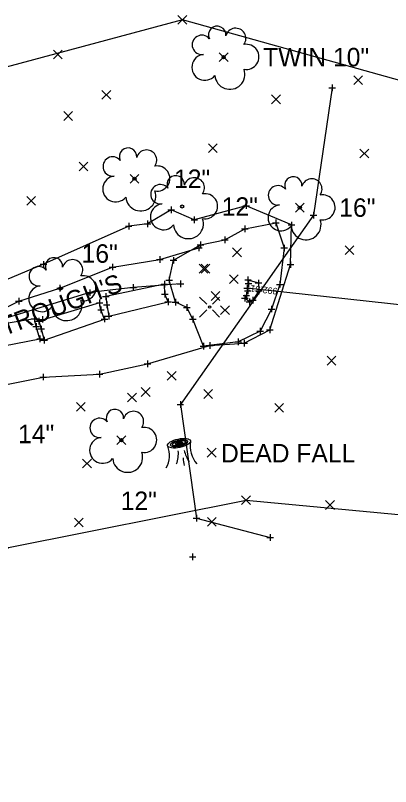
# Model space of a CAD drawing. Extents: x 160138 to 160780, y 488720 to 491073.
# Drawn here: x 160617.3 to 160674.2, y 489637.9 to 489754.9 of the extents above; entities that cross this region are included whole.
import ezdxf

# ---------------------------------------------------------------- set-up
doc = ezdxf.new("R2010")
doc.units = 0
for name, color, linetype in [('_CIVIL_CONSTRUCTION', 7, 'Continuous'), ('DR_X_Storm_Sewer', 7, 'Continuous'), ('GE_X_Alignment_500_Distances', 7, 'Continuous'), ('RD_X_Concrete_Pad', 7, 'Continuous'), ('RD_X_Text', 7, 'Continuous'), ('RS_Raster1', 7, 'Continuous'), ('RW_X_CL_100_Curve_Data', 7, 'Continuous'), ('RW_X_CL_100_Stations', 7, 'Continuous'), ('SC_Scratch1', 7, 'Continuous'), ('SV_P_Control_Cells_Set', 7, 'Continuous'), ('SV_P_Mon_Cells_Set', 7, 'Continuous'), ('SV_X_Mon_Cells_Found', 7, 'Continuous'), ('SV_X_Random_Point', 7, 'Continuous'), ('SV_X_Terrain_Boundary', 7, 'Continuous'), ('VG_X_Text', 7, 'Continuous'), ('VG_X_Tree_Line_Lt', 7, 'Continuous')]:
    doc.layers.add(name, color=color, linetype=linetype)

msp = doc.modelspace()

# ---------------------------------------------------------------- linework, layer by layer
at = {"layer": '_CIVIL_CONSTRUCTION'}
for p, q in [((160641.93, 489753.59), (160643.26, 489754.92)), ((160641.93, 489754.92), (160643.26, 489753.59)), ((160623.01, 489748.32), (160624.34, 489749.66)), ((160623.01, 489749.66), (160624.34, 489748.32)), ((160648.2, 489747.93), (160649.53, 489749.27)), ((160648.2, 489749.27), (160649.53, 489747.93)), ((160668.62, 489744.44), (160669.96, 489745.77)), ((160668.62, 489745.77), (160669.96, 489744.44)), ((160630.38, 489742.19), (160631.72, 489743.53)), ((160630.38, 489743.53), (160631.72, 489742.19)), ((160656.14, 489741.52), (160657.48, 489742.85)), ((160656.14, 489742.85), (160657.48, 489741.52)), ((160624.6, 489738.99), (160625.93, 489740.33)), ((160624.6, 489740.33), (160625.93, 489738.99)), ((160646.57, 489734.1), (160647.9, 489735.43)), ((160646.57, 489735.43), (160647.9, 489734.1)), ((160669.56, 489733.31), (160670.9, 489734.65)), ((160669.56, 489734.65), (160670.9, 489733.31)), ((160626.94, 489731.34), (160628.27, 489732.67)), ((160626.94, 489732.67), (160628.27, 489731.34)), ((160634.67, 489729.47), (160636, 489730.8)), ((160634.67, 489730.8), (160636, 489729.47)), ((160618.99, 489726.11), (160620.32, 489727.44)), ((160618.99, 489727.44), (160620.32, 489726.11)), ((160659.75, 489725.09), (160661.09, 489726.43)), ((160659.75, 489726.43), (160661.09, 489725.09)), ((160650.23, 489718.29), (160651.56, 489719.63)), ((160650.23, 489719.63), (160651.56, 489718.29)), ((160667.3, 489718.64), (160668.64, 489719.98)), ((160667.3, 489719.98), (160668.64, 489718.64)), ((160645.15, 489715.81), (160646.48, 489717.15)), ((160645.15, 489717.15), (160646.48, 489715.81)), ((160645.46, 489715.82), (160646.79, 489717.16)), ((160645.46, 489717.16), (160646.79, 489715.82)), ((160649.75, 489714.25), (160651.08, 489715.58)), ((160649.75, 489715.58), (160651.08, 489714.25)), ((160646.97, 489711.68), (160648.3, 489713.01)), ((160646.97, 489713.01), (160648.3, 489711.68)), ((160648.39, 489709.53), (160649.73, 489710.86)), ((160648.39, 489710.86), (160649.73, 489709.53)), ((160664.58, 489701.85), (160665.91, 489703.19)), ((160664.58, 489703.19), (160665.91, 489701.85)), ((160640.3, 489699.57), (160641.64, 489700.91)), ((160640.3, 489700.91), (160641.64, 489699.57)), ((160636.36, 489697.11), (160637.69, 489698.45)), ((160636.36, 489698.45), (160637.69, 489697.11)), ((160634.29, 489696.29), (160635.62, 489697.62)), ((160634.29, 489697.62), (160635.62, 489696.29)), ((160645.86, 489696.79), (160647.19, 489698.13)), ((160645.86, 489698.13), (160647.19, 489696.79)), ((160626.51, 489694.86), (160627.84, 489696.19)), ((160626.51, 489696.19), (160627.84, 489694.86)), ((160656.61, 489694.71), (160657.94, 489696.05)), ((160656.61, 489696.05), (160657.94, 489694.71)), ((160632.67, 489689.8), (160634.01, 489691.13)), ((160632.67, 489691.13), (160634.01, 489689.8)), ((160646.37, 489687.91), (160647.71, 489689.25)), ((160646.37, 489689.25), (160647.71, 489687.91)), ((160627.44, 489686.25), (160628.78, 489687.59)), ((160627.44, 489687.59), (160628.78, 489686.25)), ((160651.6, 489680.69), (160652.94, 489682.02)), ((160651.6, 489682.02), (160652.94, 489680.69)), ((160664.34, 489679.96), (160665.67, 489681.29)), ((160664.34, 489681.29), (160665.67, 489679.96)), ((160626.2, 489677.29), (160627.53, 489678.63)), ((160626.2, 489678.63), (160627.53, 489677.29)), ((160646.39, 489677.41), (160647.72, 489678.75)), ((160646.39, 489678.75), (160647.72, 489677.41))]:
    msp.add_line(p, q, dxfattribs=at)
at = {"layer": 'DR_X_Storm_Sewer'}
msp.add_line((160736.14, 489704.3), (160652.45, 489713.55), dxfattribs=at)
at = {"layer": 'GE_X_Alignment_500_Distances'}
msp.add_lwpolyline([(160606.81, 489697.08), (160621.48, 489700.05), (160630.02, 489700.49), (160637.32, 489702.04), (160646.76, 489704.84), (160651.99, 489705.18), (160655.89, 489707.19), (160659.01, 489717.1), (160659.18, 489723.12), (160652.27, 489726.05), (160644.41, 489723.92), (160640.91, 489725.41), (160637.3, 489723.29), (160634.45, 489722.96), (160621.53, 489717.15), (160606.18, 489710.76)], dxfattribs=at)
at = {"layer": 'RD_X_Concrete_Pad'}
for points in [[(160640.46, 489711.46), (160639.94, 489712.63), (160639.86, 489714.15), (160630.99, 489712.27), (160631.11, 489711.01), (160631.41, 489709.3)], [(160630.76, 489708.85), (160630.24, 489710.26), (160630.04, 489711.29), (160620.79, 489708.54), (160621.17, 489707.34), (160621.61, 489705.66)], [(160620.98, 489705.83), (160620.39, 489707.73), (160620.16, 489708.89), (160611.14, 489707.39), (160611.67, 489705.22), (160611.8, 489704.05)]]:
    msp.add_lwpolyline(points, close=True, dxfattribs=at)
at = {"layer": 'RS_Raster1'}
for p, q in [((160651.95, 489713.55), (160652.95, 489713.55)), ((160652.45, 489714.05), (160652.45, 489713.05)), ((160652.45, 489713.55), (160652.45, 489713.55)), ((160620.84, 489708.8), (160621.84, 489708.8)), ((160621.34, 489709.3), (160621.34, 489708.3)), ((160621.34, 489708.8), (160621.34, 489708.8))]:
    msp.add_line(p, q, dxfattribs=at)
at = {"layer": 'RW_X_CL_100_Curve_Data'}
msp.add_lwpolyline([(160656.8, 489723.43), (160658.06, 489719.63), (160657.41, 489714.11), (160656.13, 489710.37), (160654.42, 489707.03), (160651.09, 489705.4), (160645.8, 489704.75), (160644.2, 489708.84), (160643.27, 489710.59), (160641.57, 489711.39), (160640.61, 489714.75), (160641.25, 489717.76), (160645.36, 489720.12), (160649.06, 489720.86), (160652.09, 489722.54)], close=True, dxfattribs=at)
at = {"layer": 'RW_X_CL_100_Stations'}
msp.add_lwpolyline([(160652.52, 489713.11), (160652.62, 489714.25), (160652.56, 489714.79), (160654.15, 489714.32), (160654.21, 489713.12), (160653.28, 489711.73), (160652.77, 489711.46), (160652.08, 489712.01), (160652.31, 489712.41)], close=True, dxfattribs=at)
at = {"layer": 'SC_Scratch1'}
msp.add_line((160642.46, 489688.49), (160642.46, 489688.49), dxfattribs=at)
for centre in [(160648.86, 489748.6), (160635.33, 489730.14), (160642.57, 489725.92), (160660.42, 489725.76), (160624.1, 489713.48), (160633.34, 489690.47)]:
    msp.add_circle(centre, 0.24, dxfattribs=at)
for centre, radius, start, end in [((160647.88, 489751.97), 1.32, 354.0047, 205.9741), ((160650.69, 489751.43), 1.55, 323.83, 165.0376), ((160645.55, 489750.46), 1.47, 39.0625, 279.5412), ((160652.32, 489748.63), 1.91, 259.1453, 101.4596), ((160646.01, 489747.05), 1.97, 96.1722, 320.5737), ((160649.81, 489745.99), 2.28, 184.9476, 19.4572), ((160634.35, 489733.5), 1.32, 354.0047, 205.9741), ((160632.02, 489732), 1.47, 39.0625, 279.5412), ((160637.16, 489732.96), 1.55, 323.83, 165.0376), ((160638.79, 489730.17), 1.91, 259.1453, 101.4596), ((160632.48, 489728.59), 1.97, 96.1722, 320.5737), ((160641.59, 489729.29), 1.32, 354.0047, 205.9741), ((160644.4, 489728.75), 1.55, 323.83, 165.0376), ((160659.44, 489729.13), 1.32, 354.0047, 205.9741), ((160662.25, 489728.59), 1.55, 323.83, 165.0376), ((160639.26, 489727.79), 1.47, 39.0625, 279.5412), ((160657.11, 489727.62), 1.47, 39.0625, 279.5412), ((160636.28, 489727.53), 2.28, 184.9476, 19.4572), ((160646.03, 489725.96), 1.91, 259.1453, 101.4596), ((160663.88, 489725.79), 1.91, 259.1453, 101.4596), ((160639.72, 489724.37), 1.97, 96.1722, 320.5737), ((160657.57, 489724.21), 1.97, 96.1722, 320.5737), ((160643.52, 489723.32), 2.28, 184.9476, 19.4572), ((160661.37, 489723.15), 2.28, 184.9476, 19.4572), ((160623.11, 489716.85), 1.32, 354.0047, 205.9741), ((160625.92, 489716.31), 1.55, 323.83, 165.0376), ((160620.79, 489715.35), 1.47, 39.0625, 279.5412), ((160627.56, 489713.52), 1.91, 259.1453, 101.4596), ((160621.24, 489711.93), 1.97, 96.1722, 320.5737), ((160625.04, 489710.88), 2.28, 184.9476, 19.4572), ((160632.36, 489693.83), 1.32, 354.0047, 205.9741), ((160635.17, 489693.3), 1.55, 323.83, 165.0376), ((160630.03, 489692.33), 1.47, 39.0625, 279.5412), ((160636.8, 489690.5), 1.91, 259.1453, 101.4596), ((160630.49, 489688.92), 1.97, 96.1722, 320.5737), ((160648.07, 489689.63), 4.29, 171.4106, 219.9194), ((160636.63, 489688.15), 4, 331.5338, 20.9269), ((160648.97, 489690.55), 6.32, 194.9653, 212.1216), ((160634.29, 489687.86), 2.28, 184.9476, 19.4572), ((160636.94, 489688.52), 5.05, 340.7938, 3.5481), ((160646.37, 489687.69), 3.64, 178.7926, 197.1224)]:
    msp.add_arc(centre, radius, start, end, dxfattribs=at)
for major_axis in [(1.74, 0.37), (1.3, 0.28), (0.976, 0.211), (0.549, 0.119), (0.309, 0.067)]:
    msp.add_ellipse((160642.09, 489690), major_axis=major_axis, ratio=0.36865, dxfattribs=at)
at = {"layer": 'SV_P_Control_Cells_Set'}
msp.add_lwpolyline([(160570.79, 489697.1), (160575.87, 489695.84), (160582.13, 489698.19), (160589.99, 489701.08), (160597.61, 489703.89), (160611.48, 489708.49), (160617.77, 489711.56), (160624.02, 489713.54), (160631.98, 489716.74), (160639.19, 489717.9), (160645.11, 489719.67)], dxfattribs=at)
at = {"layer": 'SV_P_Mon_Cells_Set'}
msp.add_lwpolyline([(160642.3, 489714.2), (160635.13, 489713.64), (160628.55, 489712.85), (160611, 489707.49), (160597, 489702.59), (160583.66, 489697.45), (160573.76, 489689.28), (160563.37, 489687.48)], dxfattribs=at)
at = {"layer": 'SV_X_Mon_Cells_Found'}
for p, q in [((160645.22, 489712.17), (160646.31, 489711.08)), ((160647.15, 489711.08), (160648.24, 489712.17)), ((160645.22, 489709.15), (160646.31, 489710.24)), ((160647.15, 489710.24), (160648.24, 489709.15))]:
    msp.add_line(p, q, dxfattribs=at)
msp.add_circle((160646.73, 489710.67), 0.17, dxfattribs=at)
at = {"layer": 'SV_X_Random_Point'}
for p, q in [((160664.84, 489743.92), (160665.84, 489743.92)), ((160665.34, 489744.42), (160665.34, 489743.42)), ((160665.34, 489743.92), (160665.34, 489743.92)), ((160652.27, 489726.55), (160652.27, 489725.55)), ((160640.41, 489725.41), (160641.41, 489725.41)), ((160640.91, 489725.91), (160640.91, 489724.91)), ((160640.91, 489725.41), (160640.91, 489725.41)), ((160651.77, 489726.05), (160652.77, 489726.05)), ((160652.27, 489726.05), (160652.27, 489726.05)), ((160644.41, 489724.42), (160644.41, 489723.42)), ((160662.01, 489724.6), (160663.01, 489724.6)), ((160662.51, 489725.1), (160662.51, 489724.1)), ((160662.51, 489724.6), (160662.51, 489724.6)), ((160633.95, 489722.96), (160634.95, 489722.96)), ((160634.45, 489723.46), (160634.45, 489722.46)), ((160634.45, 489722.96), (160634.45, 489722.96)), ((160636.8, 489723.29), (160637.8, 489723.29)), ((160637.3, 489723.79), (160637.3, 489722.79)), ((160637.3, 489723.29), (160637.3, 489723.29)), ((160643.91, 489723.92), (160644.91, 489723.92)), ((160644.41, 489723.92), (160644.41, 489723.92)), ((160652.09, 489723.04), (160652.09, 489722.04)), ((160656.3, 489723.43), (160657.3, 489723.43)), ((160656.8, 489723.93), (160656.8, 489722.93)), ((160656.8, 489723.43), (160656.8, 489723.43)), ((160658.68, 489723.12), (160659.68, 489723.12)), ((160659.18, 489723.62), (160659.18, 489722.62)), ((160659.18, 489723.12), (160659.18, 489723.12)), ((160651.59, 489722.54), (160652.59, 489722.54)), ((160652.09, 489722.54), (160652.09, 489722.54)), ((160645.36, 489720.62), (160645.36, 489719.62)), ((160648.56, 489720.86), (160649.56, 489720.86)), ((160649.06, 489721.36), (160649.06, 489720.36)), ((160649.06, 489720.86), (160649.06, 489720.86)), ((160644.61, 489719.67), (160645.61, 489719.67)), ((160644.86, 489720.12), (160645.86, 489720.12)), ((160645.11, 489720.17), (160645.11, 489719.17)), ((160645.11, 489719.67), (160645.11, 489719.67)), ((160645.36, 489720.12), (160645.36, 489720.12)), ((160657.56, 489719.63), (160658.56, 489719.63)), ((160658.06, 489720.13), (160658.06, 489719.13)), ((160658.06, 489719.63), (160658.06, 489719.63)), ((160639.19, 489718.4), (160639.19, 489717.4)), ((160641.25, 489718.26), (160641.25, 489717.26)), ((160621.03, 489717.15), (160622.03, 489717.15)), ((160621.53, 489717.65), (160621.53, 489716.65)), ((160621.53, 489717.15), (160621.53, 489717.15)), ((160631.98, 489717.24), (160631.98, 489716.24)), ((160638.69, 489717.9), (160639.69, 489717.9)), ((160639.19, 489717.9), (160639.19, 489717.9)), ((160640.75, 489717.76), (160641.75, 489717.76)), ((160641.25, 489717.76), (160641.25, 489717.76)), ((160658.51, 489717.1), (160659.51, 489717.1)), ((160659.01, 489717.6), (160659.01, 489716.6)), ((160659.01, 489717.1), (160659.01, 489717.1)), ((160631.48, 489716.74), (160632.48, 489716.74)), ((160631.98, 489716.74), (160631.98, 489716.74)), ((160639.86, 489714.65), (160639.86, 489713.65)), ((160640.11, 489714.75), (160641.11, 489714.75)), ((160640.61, 489715.25), (160640.61, 489714.25)), ((160640.61, 489714.75), (160640.61, 489714.75)), ((160642.3, 489714.7), (160642.3, 489713.7)), ((160652.06, 489714.79), (160653.06, 489714.79)), ((160652.56, 489715.29), (160652.56, 489714.29)), ((160652.56, 489714.79), (160652.56, 489714.79)), ((160652.62, 489714.75), (160652.62, 489713.75)), ((160654.15, 489714.82), (160654.15, 489713.82)), ((160623.52, 489713.54), (160624.52, 489713.54)), ((160624.02, 489714.04), (160624.02, 489713.04)), ((160624.02, 489713.54), (160624.02, 489713.54)), ((160634.63, 489713.64), (160635.63, 489713.64)), ((160635.13, 489714.14), (160635.13, 489713.14)), ((160635.13, 489713.64), (160635.13, 489713.64)), ((160639.36, 489714.15), (160640.36, 489714.15)), ((160639.86, 489714.15), (160639.86, 489714.15)), ((160641.8, 489714.2), (160642.8, 489714.2)), ((160642.3, 489714.2), (160642.3, 489714.2)), ((160652.12, 489714.25), (160653.12, 489714.25)), ((160652.52, 489713.61), (160652.52, 489712.61)), ((160652.62, 489714.25), (160652.62, 489714.25)), ((160653.65, 489714.32), (160654.65, 489714.32)), ((160654.15, 489714.32), (160654.15, 489714.32)), ((160654.21, 489713.62), (160654.21, 489712.62)), ((160656.91, 489714.11), (160657.91, 489714.11)), ((160657.41, 489714.61), (160657.41, 489713.61)), ((160657.41, 489714.11), (160657.41, 489714.11)), ((160628.05, 489712.85), (160629.05, 489712.85)), ((160628.55, 489713.35), (160628.55, 489712.35)), ((160628.55, 489712.85), (160628.55, 489712.85)), ((160630.99, 489712.77), (160630.99, 489711.77)), ((160639.44, 489712.63), (160640.44, 489712.63)), ((160639.94, 489713.13), (160639.94, 489712.13)), ((160639.94, 489712.63), (160639.94, 489712.63)), ((160651.81, 489712.41), (160652.81, 489712.41)), ((160652.02, 489713.11), (160653.02, 489713.11)), ((160652.08, 489712.51), (160652.08, 489711.51)), ((160652.31, 489712.91), (160652.31, 489711.91)), ((160652.31, 489712.41), (160652.31, 489712.41)), ((160652.52, 489713.11), (160652.52, 489713.11)), ((160653.71, 489713.12), (160654.71, 489713.12)), ((160654.21, 489713.12), (160654.21, 489713.12)), ((160617.27, 489711.56), (160618.27, 489711.56)), ((160617.77, 489712.06), (160617.77, 489711.06)), ((160617.77, 489711.56), (160617.77, 489711.56)), ((160629.54, 489711.29), (160630.54, 489711.29)), ((160630.04, 489711.79), (160630.04, 489710.79)), ((160630.04, 489711.29), (160630.04, 489711.29)), ((160630.49, 489712.27), (160631.49, 489712.27)), ((160630.99, 489712.27), (160630.99, 489712.27)), ((160631.11, 489711.51), (160631.11, 489710.51)), ((160639.96, 489711.46), (160640.96, 489711.46)), ((160640.46, 489711.96), (160640.46, 489710.96)), ((160640.46, 489711.46), (160640.46, 489711.46)), ((160641.07, 489711.39), (160642.07, 489711.39)), ((160641.57, 489711.89), (160641.57, 489710.89)), ((160641.57, 489711.39), (160641.57, 489711.39)), ((160651.58, 489712.01), (160652.58, 489712.01)), ((160652.08, 489712.01), (160652.08, 489712.01)), ((160652.27, 489711.46), (160653.27, 489711.46)), ((160652.77, 489711.96), (160652.77, 489710.96)), ((160652.77, 489711.46), (160652.77, 489711.46)), ((160652.78, 489711.73), (160653.78, 489711.73)), ((160653.28, 489712.23), (160653.28, 489711.23)), ((160653.28, 489711.73), (160653.28, 489711.73)), ((160629.74, 489710.26), (160630.74, 489710.26)), ((160630.24, 489710.76), (160630.24, 489709.76)), ((160630.24, 489710.26), (160630.24, 489710.26)), ((160630.61, 489711.01), (160631.61, 489711.01)), ((160631.11, 489711.01), (160631.11, 489711.01)), ((160642.77, 489710.59), (160643.77, 489710.59)), ((160643.27, 489711.09), (160643.27, 489710.09)), ((160643.27, 489710.59), (160643.27, 489710.59)), ((160655.63, 489710.37), (160656.63, 489710.37)), ((160656.13, 489710.87), (160656.13, 489709.87)), ((160656.13, 489710.37), (160656.13, 489710.37)), ((160619.66, 489708.89), (160620.66, 489708.89)), ((160620.16, 489709.39), (160620.16, 489708.39)), ((160620.16, 489708.89), (160620.16, 489708.89)), ((160620.79, 489709.04), (160620.79, 489708.04)), ((160630.26, 489708.85), (160631.26, 489708.85)), ((160630.76, 489709.35), (160630.76, 489708.35)), ((160630.76, 489708.85), (160630.76, 489708.85)), ((160630.91, 489709.3), (160631.91, 489709.3)), ((160631.41, 489709.8), (160631.41, 489708.8)), ((160631.41, 489709.3), (160631.41, 489709.3)), ((160643.7, 489708.84), (160644.7, 489708.84)), ((160644.2, 489709.34), (160644.2, 489708.34)), ((160644.2, 489708.84), (160644.2, 489708.84)), ((160619.89, 489707.73), (160620.89, 489707.73)), ((160620.29, 489708.54), (160621.29, 489708.54)), ((160620.39, 489708.23), (160620.39, 489707.23)), ((160620.39, 489707.73), (160620.39, 489707.73)), ((160620.79, 489708.54), (160620.79, 489708.54)), ((160621.17, 489707.84), (160621.17, 489706.84)), ((160655.89, 489707.69), (160655.89, 489706.69)), ((160620.67, 489707.34), (160621.67, 489707.34)), ((160621.17, 489707.34), (160621.17, 489707.34)), ((160653.92, 489707.03), (160654.92, 489707.03)), ((160654.42, 489707.53), (160654.42, 489706.53)), ((160654.42, 489707.03), (160654.42, 489707.03)), ((160655.39, 489707.19), (160656.39, 489707.19)), ((160655.89, 489707.19), (160655.89, 489707.19)), ((160620.48, 489705.83), (160621.48, 489705.83)), ((160620.98, 489706.33), (160620.98, 489705.33)), ((160620.98, 489705.83), (160620.98, 489705.83)), ((160621.11, 489705.66), (160622.11, 489705.66)), ((160621.61, 489706.16), (160621.61, 489705.16)), ((160621.61, 489705.66), (160621.61, 489705.66)), ((160646.76, 489705.34), (160646.76, 489704.34)), ((160650.59, 489705.4), (160651.59, 489705.4)), ((160651.09, 489705.9), (160651.09, 489704.9)), ((160651.09, 489705.4), (160651.09, 489705.4)), ((160651.99, 489705.68), (160651.99, 489704.68)), ((160645.3, 489704.75), (160646.3, 489704.75)), ((160645.8, 489705.25), (160645.8, 489704.25)), ((160645.8, 489704.75), (160645.8, 489704.75)), ((160646.26, 489704.84), (160647.26, 489704.84)), ((160646.76, 489704.84), (160646.76, 489704.84)), ((160651.49, 489705.18), (160652.49, 489705.18)), ((160651.99, 489705.18), (160651.99, 489705.18)), ((160636.82, 489702.04), (160637.82, 489702.04)), ((160637.32, 489702.54), (160637.32, 489701.54)), ((160637.32, 489702.04), (160637.32, 489702.04)), ((160630.02, 489700.99), (160630.02, 489699.99)), ((160620.98, 489700.05), (160621.98, 489700.05)), ((160621.48, 489700.55), (160621.48, 489699.55)), ((160621.48, 489700.05), (160621.48, 489700.05)), ((160629.52, 489700.49), (160630.52, 489700.49)), ((160630.02, 489700.49), (160630.02, 489700.49)), ((160642.29, 489696.37), (160642.29, 489695.37)), ((160641.79, 489695.87), (160642.79, 489695.87)), ((160642.29, 489695.87), (160642.29, 489695.87)), ((160644.26, 489678.62), (160645.26, 489678.62)), ((160644.76, 489679.12), (160644.76, 489678.12)), ((160644.76, 489678.62), (160644.76, 489678.62)), ((160655.92, 489676.19), (160655.92, 489675.19)), ((160655.42, 489675.69), (160656.42, 489675.69)), ((160655.92, 489675.69), (160655.92, 489675.69)), ((160643.66, 489672.75), (160644.66, 489672.75)), ((160644.16, 489673.25), (160644.16, 489672.25)), ((160644.16, 489672.75), (160644.16, 489672.75))]:
    msp.add_line(p, q, dxfattribs=at)
at = {"layer": 'SV_X_Terrain_Boundary'}
msp.add_lwpolyline([(160514.91, 489637.89), (160547.86, 489638.24), (160565.43, 489639.08), (160616.19, 489674.18), (160652.27, 489681.36), (160684.01, 489678.35), (160707.03, 489678.82), (160736.83, 489679.67), (160750.02, 489679.19), (160759.85, 489681.65), (160765.27, 489684.51), (160772.9, 489693.36), (160771.25, 489707.54), (160769.28, 489717.03), (160767.49, 489724.4), (160754.69, 489734.76), (160746.2, 489734.78), (160717.64, 489733.31), (160642.6, 489754.26), (160573.96, 489735.82), (160560.41, 489729.32), (160491.05, 489700.61)], dxfattribs=at)
at = {"layer": 'VG_X_Tree_Line_Lt'}
msp.add_lwpolyline([(160665.34, 489743.92), (160662.51, 489724.6), (160642.29, 489695.87), (160644.76, 489678.62), (160655.92, 489675.69)], dxfattribs=at)

# ---------------------------------------------------------------- texts
at = {"layer": 'RD_X_Text'}
msp.add_text("UNDERCUT CONCRETE TROUGH'S", height=2.8, rotation=20.8489, dxfattribs=at).set_placement((160574.36, 489690.57))
at = {"layer": 'SC_Scratch1'}
msp.add_text("992.51'", height=1, rotation=173.6965, dxfattribs=at).set_placement((160657.08, 489713.54))
at = {"layer": 'VG_X_Text'}
for s, p in [('TWIN 10"', (160654.86, 489747.2)), ('12"', (160641.33, 489728.74)), ('12"', (160648.57, 489724.52)), ('16"', (160666.42, 489724.36)), ('16"', (160627.3, 489717.39)), ('14"', (160617.66, 489690.01)), ('DEAD FALL', (160648.46, 489687.09)), ('12"', (160633.23, 489679.86))]:
    msp.add_text(s, height=2.8, dxfattribs=at).set_placement(p)

doc.saveas('drawing.dxf')
